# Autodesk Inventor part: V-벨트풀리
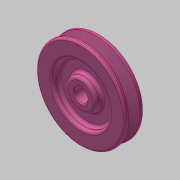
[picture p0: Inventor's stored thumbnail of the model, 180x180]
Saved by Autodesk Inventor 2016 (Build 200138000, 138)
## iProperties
Created: 2020-05
Part Number: V-벨트풀리
Material: 알루미늄 6061
Document SubType Name: Modeling
Designer: mduedu
Density: 1 g/cm^3
Appearance: 분홍색
Author: mduedu
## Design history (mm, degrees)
sketch "스케치1"
  geometry: L1 (-10, 0)-(10, 0); L2 (10, 47.5)-(-10, 47.5); L3 (-5.976, 47.5)-(-2.154, 35); L4 (-2.154, 35)-(2.154, 35); L5 (2.154, 35)-(5.976, 47.5); L6 (0, 0)-(0, 47.5); L7 (-10, 30)-(-3, 30); L8 (-3, 30)-(-3, 16); L9 (-3, 16)-(-10, 16); L10 (-10, 47.5)-(-10, 30); L11 (-10, 16)-(-10, 0); L12 (10, 30)-(3, 30); L13 (3, 30)-(3, 16); L14 (3, 16)-(10, 16); L15 (10, 0)-(10, 16); L16 (10, 30)-(10, 47.5); L17 (-4.6, 43)-(4.6, 43); 2 further points
  constraints: 34 end point, 6 parallel, 6 perpendicular, 4 point on line, 4 symmetric about line, 3 midpoint, 2 horizontal, 1 coincident, 1 collinear, 1 equal length, 1 vertical alignment
  dimensions: "d0" = 95 diameter of L2 L1; "d2" = 20 distance between parallel lines of L16 L10; "d3" = 6 distance between parallel lines of L13 L8; "d4" = 32 diameter of L14 L1; "d5" = 60 diameter of L12 L1; "d6" = 4.5 distance between parallel lines of L17 L2; "d7" = 8 distance between parallel lines of L4 L17; "d8" = 34 deg angle of L5 L3; "d9" = 9.2 distance of L17.start L17.end
revolve "회전1" sketch "스케치1" stored, may be unused: angle "d10" = 90 deg
sketch "스케치2"
  geometry: L1 (-2.5, 6.538)-(2.5, 6.538); L2 (2.5, 6.538)-(2.5, 9.3); L3 (2.5, 9.3)-(-2.5, 9.3); L4 (-2.5, 9.3)-(-2.5, 6.538); A1 r 7 centre (0, 0) between (-2.5, 6.538) and (2.5, 6.538); 1 further point
  constraints: 8 end point, 2 parallel, 2 point on circle, 1 centre point, 1 coincident, 1 horizontal, 1 perpendicular
  dimensions: "d11" = 14 diameter of A1; "d13" = 16.3 dimension on A1 L3; "d14" = 5 distance of L2.end L3.end
extrude "돌출1" cut sketch "스케치2" stored distance "d15" = 10; taper "d16" = 0 deg
chamfer "모따기1" distance "d17" = 1; stored, may be unused: second distance "d18" = 2, angle "d19" = 45 deg
fillet "모깎기1" dims "d20" = 3
fillet "모깎기2" dims "d21" = 2
fillet "모깎기3" dims "d22" = 1
fillet "모깎기4" dims "d23" = 0.5
fillet "모깎기5" dims "d24" = 3
node "솔리드1"
